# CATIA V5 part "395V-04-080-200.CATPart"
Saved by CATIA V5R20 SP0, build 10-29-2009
Part number: 395V-04-080-200
Source: Unknown
Property "A": "40.000"
Property "ARTICLENO": "395V-04-080-200"
Property "BOMINFO": "395V-04-080-200"
Property "CODE": "395V-04-080-200"
Property "D": "63.000"
Property "D1": "23.000"
Property "D2": "33.000"
Property "D3": "90.000"
Property "FORM": "B"
Property "L": "200.000"
Property "L1": "20.000"
Property "L2": "78.000"
Property "L3": "50.000"
Property "L4": "12.000"
Property "LINA": "395V-04-080-200"
Property "MAXLOAD": "8000 Kg"
Property "MDW": "16000 Kg"
Property "NB": "395V-04-080-200"
Property "NBSYN": "$CODE."
Property "NN": "395V"
Property "NT": "VDI 3366 Lifting Brackets"
Property "SUPPLIER": "CF"
Property "T": "21.500"
Property "W": "80.000"
Bounding box of the stored display mesh (mm): x -40 to 40, y 0 to 200, z -40 to 40
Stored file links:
  C:\Users\Utente\Desktop\3D files 395V\395V-04-080-200.CATPart
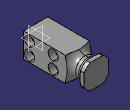
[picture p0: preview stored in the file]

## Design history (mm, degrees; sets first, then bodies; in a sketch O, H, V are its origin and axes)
Body1 "Geometry.1" (main body)
  Solid1 "395V-04-080-200.catpart": solid without history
